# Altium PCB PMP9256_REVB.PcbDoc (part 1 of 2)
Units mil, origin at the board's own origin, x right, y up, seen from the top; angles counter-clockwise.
Board outline 5025 x 2070 mil, 4 copper layers (Top Layer, Signal Layer 1, Signal Layer 2, Bottom Layer), stack 61.2 mil thick; 115 components, 45 nets, 247 pads, 260 vias.
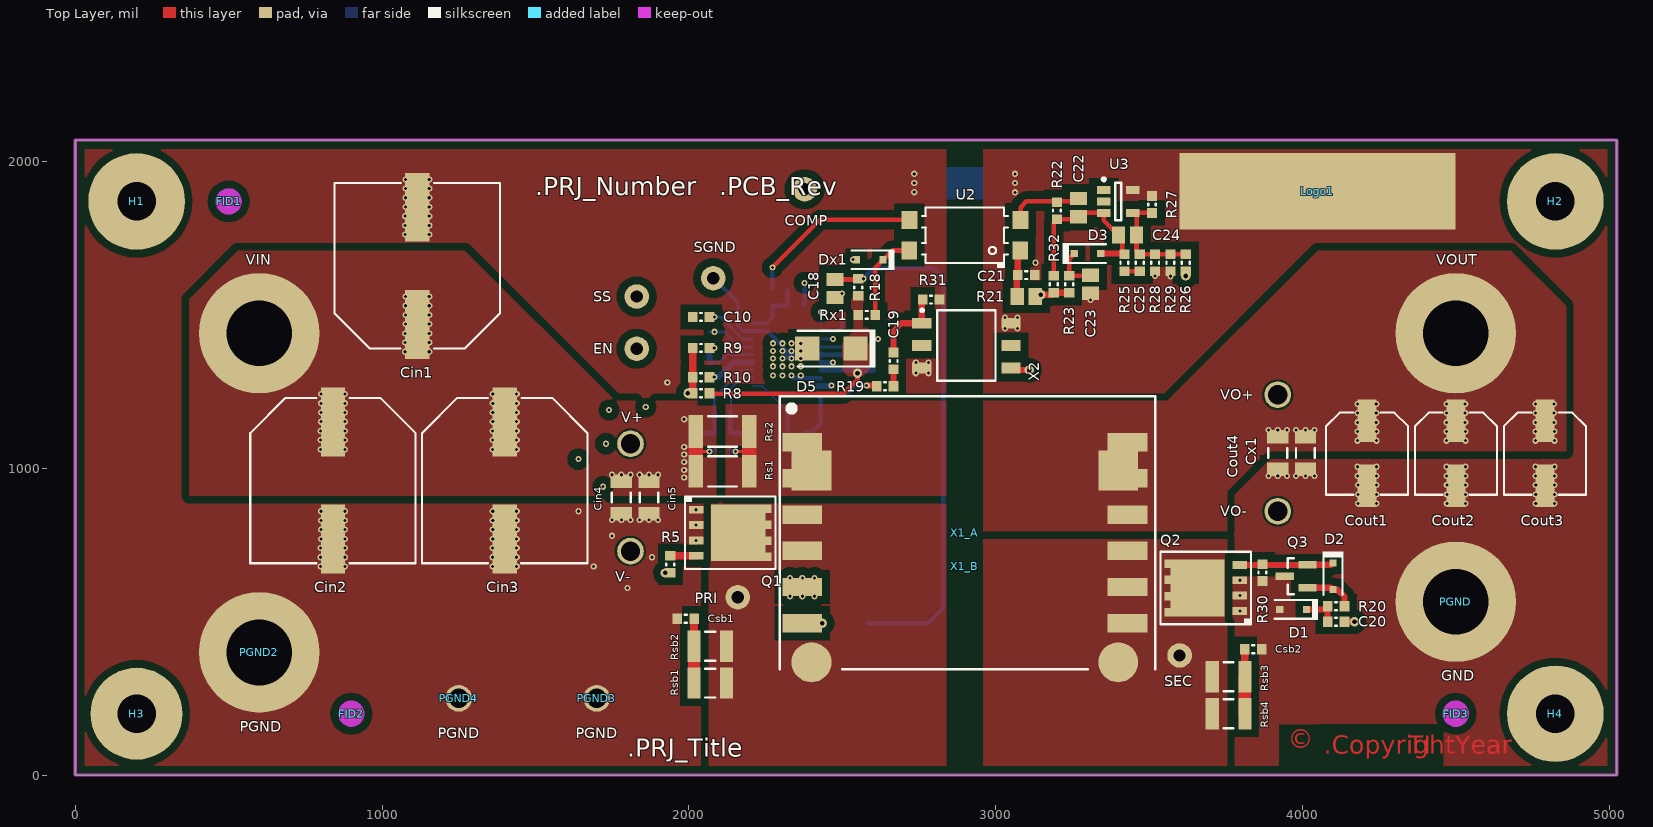
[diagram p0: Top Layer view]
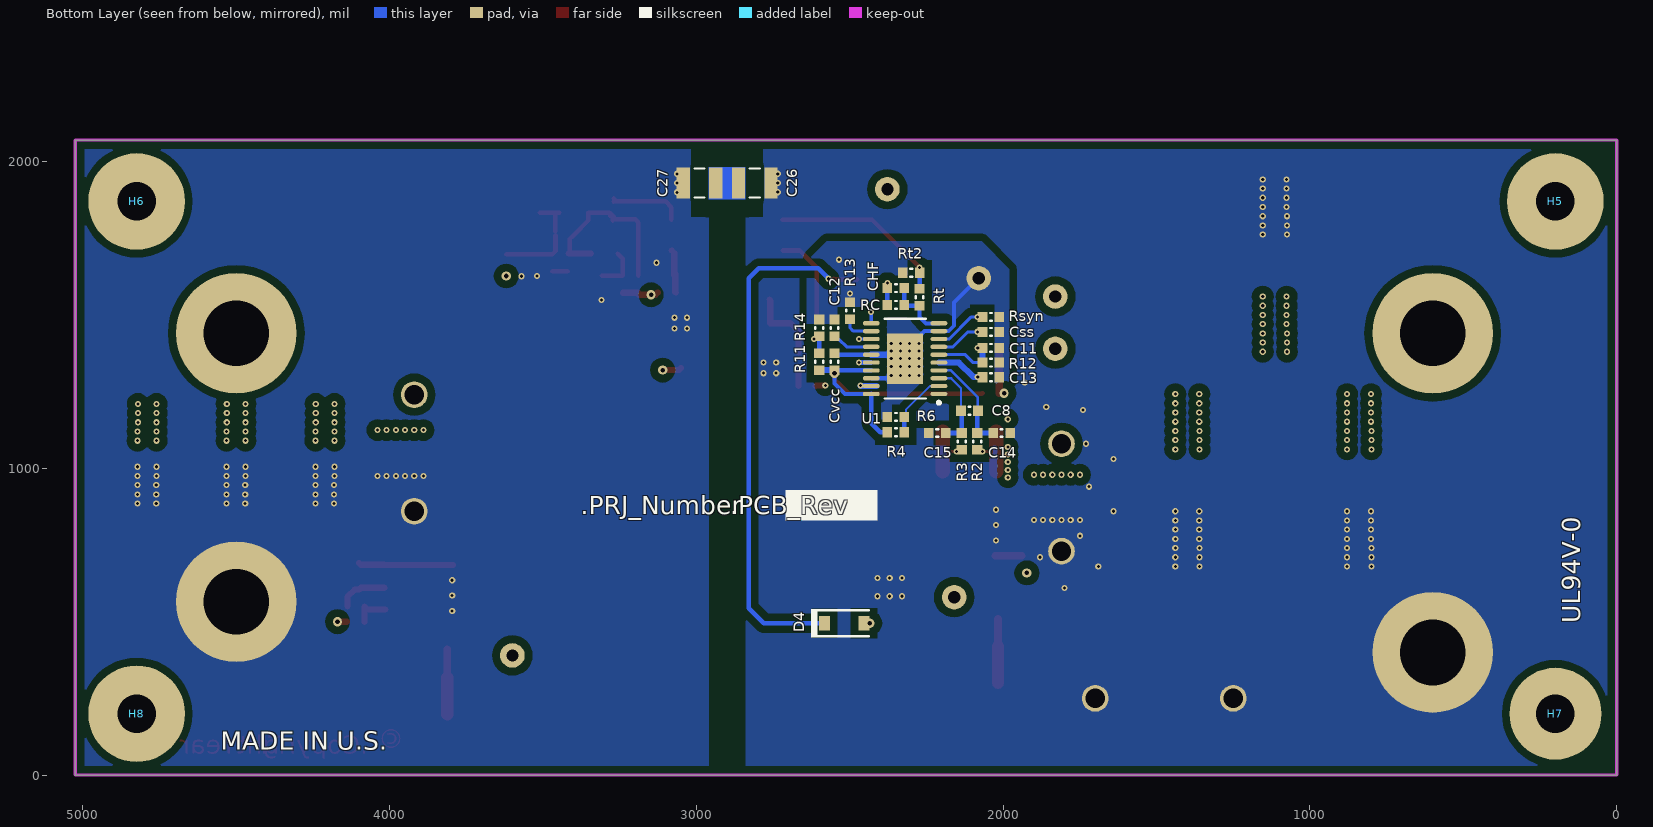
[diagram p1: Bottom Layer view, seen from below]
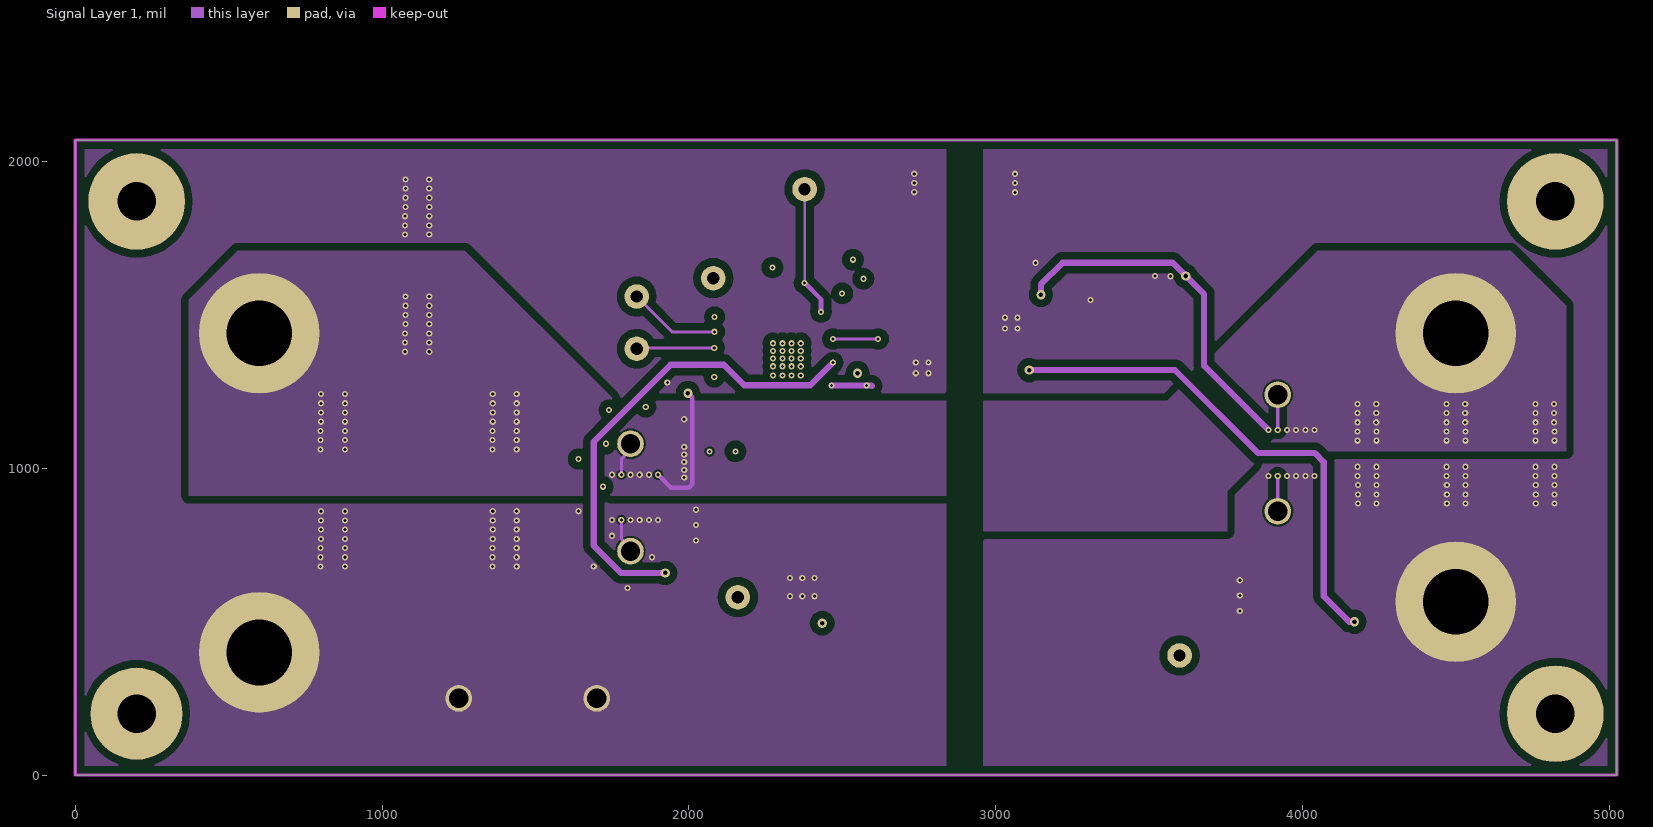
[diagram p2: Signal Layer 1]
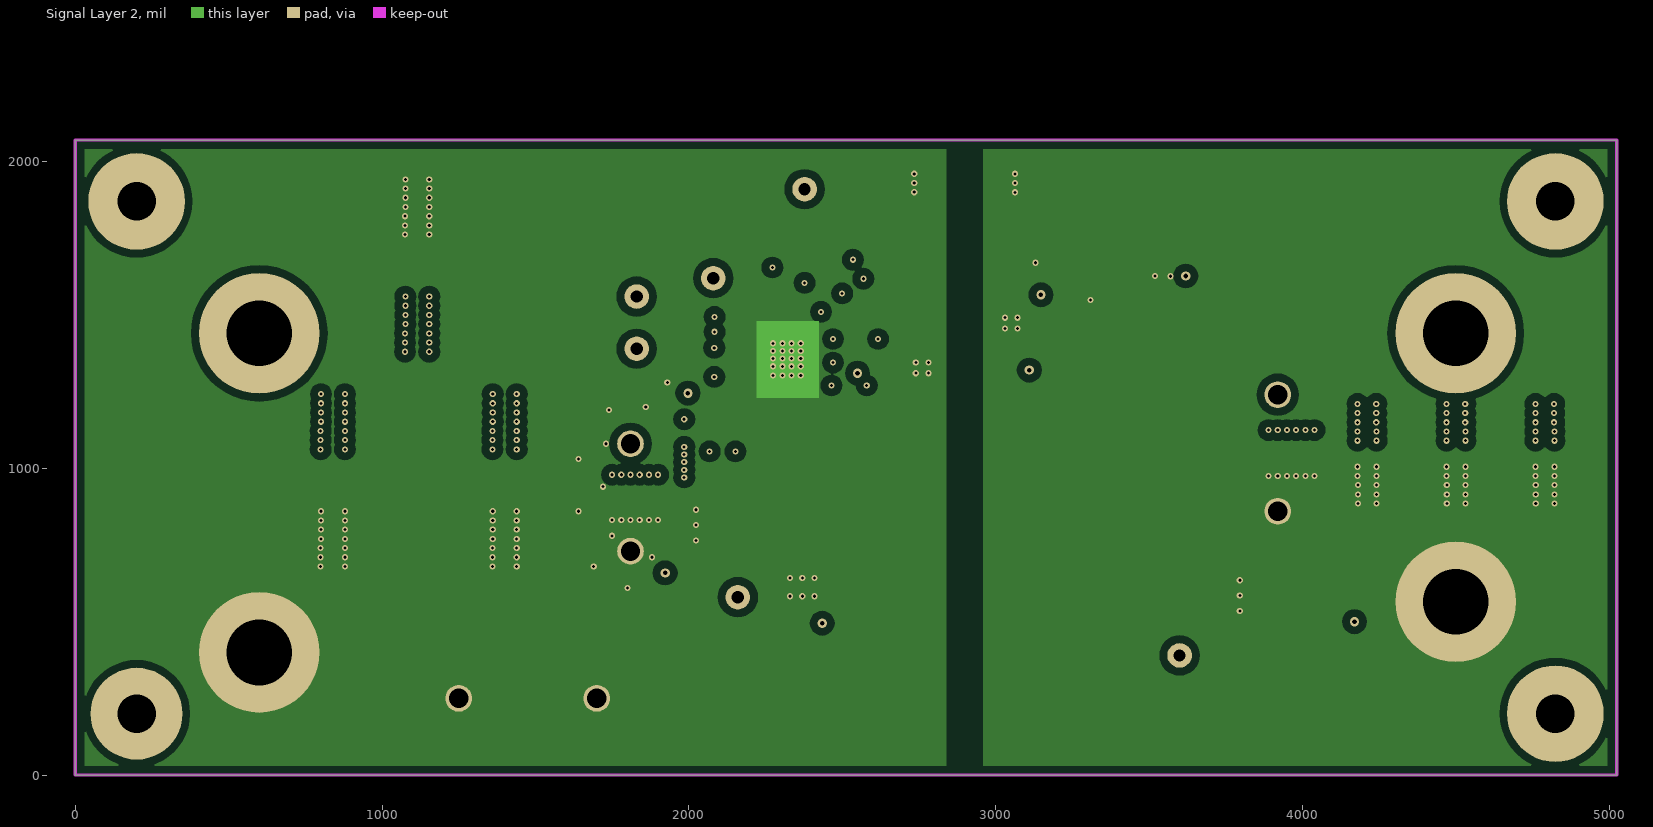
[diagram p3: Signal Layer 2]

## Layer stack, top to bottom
Top Solder: solder mask 0.4, Solder Resist, Dk 3.5
Top Layer: signal copper 1.4
Dielectric1: core 10, FR-4, Dk 4.8
Signal Layer 1: signal copper 0.7
Dielectric 3: prepreg 37, FR-4, Dk 4.2
Signal Layer 2: signal copper 0.7
Dielectric 2: core 10, FR-4, Dk 4.2
Bottom Layer: signal copper 1.4
Bottom Solder: solder mask 0.4, Solder Resist, Dk 3.5

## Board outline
0,0 5025,0 5025,2070 0,2070

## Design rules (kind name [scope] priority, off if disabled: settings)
AcuteAngle [All] p1: minimum=4.50000000000000E+0001 checktracksonly=FALSE
AssemblyTestPointUsage [All] p1: valid=2
Clearance Clearance_1 [InNet('ISO')] p1: gap=60
Clearance Clearance_Keepouts [((IsTrack Or IsArc) And Not InPoly) And IsFree and IsKeepOut vs ((IsTrack Or IsArc) And Not InPoly) And IsFree and IsKeepOut] p2: gap=0
Clearance Clearance_BoardEdge_MountingHoles [OnCopper and InComponentClass('Mounting Holes') vs IsKeepOut] p3: gap=35
Clearance Clearance_BoardEdge_Poly [OnCopper and InPoly vs IsKeepOut] p4: gap=25
Clearance Clearance_BoardEdge [OnCopper and Not InComponentClass('Logo') and not InComponentClass('FiducialMark') and not InRegion(1000,500,4000,800) and Not IsKeepout vs IsKeepOut] p5: gap=75
Clearance Clearance_Poly [InPolygon] p6: gap=25
Clearance [All] p7: gap=7.87
ComponentClearance ComponentClearance_X1 [HasFootprint('PA2398NL') vs HasFootprint('PA6605-AL')] p1: gap=0 collisioncheckmode=3 verticalgap=0 showdistances=FALSE
ComponentClearance ComponentClearance_MountingHoles_FiducialMarks [InComponentClass('Mounting Holes') vs InComponentClass('FiducialMark')] p2: gap=50 collisioncheckmode=3 verticalgap=10 showdistances=FALSE
ComponentClearance ComponentClearance_Shunt [InComponentClass('Header') vs InComponentClass('Shunt')] p3: gap=0 collisioncheckmode=3 verticalgap=0 showdistances=FALSE
ComponentClearance ComponentClearance_Logo [InComponentClass('Logo')] p4: gap=50 collisioncheckmode=3 verticalgap=10 showdistances=FALSE
ComponentClearance ComponentClearance_ScrewToNut [(HasFootprint('NY PMS 440 0025 PH')) vs (HasFootprint('Keystone_1902C'))] p5: gap=5 collisioncheckmode=3 verticalgap=10 showdistances=FALSE
ComponentClearance ComponentClearance_MountingHoles [InComponentClass('Mounting Holes')] p6: gap=150 collisioncheckmode=3 verticalgap=100000 showdistances=FALSE
ComponentClearance ComponentClearance_SmallPassives [HasFootprint('0201*') or HasFootprint('0402*') or HasFootprint('0508') or HasFootprint('0603*') or HasFootprint('0612') or HasFootprint('0805*') or HasFootprint('0815*') or HasFootprint('0830*') or HasFootprint('1206*') or HasFootprint('1210*') or HasFootprint('1808*') or HasFootprint('1812*') or HasFootprint('1825*') or HasFootprint('2010*') or HasFootprint('2220*') or HasFootprint('2225*') or HasFootprint('2512*') or HasFootprint('2728*') or HasFootprint('3518*') vs HasFootprint('0201*') or HasFootprint('0402*') or HasFootprint('0508') or HasFootprint('0603*') or HasFootprint('0612') or HasFootprint('0805*') or HasFootprint('0815*') or HasFootprint('0830*') or HasFootprint('1206*') or HasFootprint('1210*') or HasFootprint('1808*') or HasFootprint('1812*') or HasFootprint('1825*') or HasFootprint('2010*') or HasFootprint('2220*') or HasFootprint('2225*') or HasFootprint('2512*') or HasFootprint('2728*') or HasFootprint('3518*')] p7: gap=10 collisioncheckmode=3 verticalgap=10 showdistances=FALSE
ComponentClearance ComponentClearance_THtoSMT [IsThruComponent vs IsSMTComponent] p8: gap=40 collisioncheckmode=3 verticalgap=30 showdistances=FALSE
ComponentClearance ComponentClearance_THtoTH [IsThruComponent vs IsThruComponent] p9: gap=50 collisioncheckmode=3 verticalgap=30 showdistances=FALSE
ComponentClearance [All] p10: gap=20 collisioncheckmode=3 verticalgap=10 showdistances=FALSE
DiffPairsRouting [All] p1: maxlimit=100 minlimit=10 mostfreqgap=10 toplayer_minwidth=15 toplayer_maxwidth=15 toplayer_prefwidth=15 midlayer1_minwidth=15 midlayer1_maxwidth=15 midlayer1_prefwidth=15 midlayer2_minwidth=15 midlayer2_maxwidth=15 midlayer2_prefwidth=15 bottomlayer_minwidth=15 bottomlayer_maxwidth=15 bottomlayer_prefwidth=15 maxuncoupledlength=1000
FabricationTestPointUsage TestPointUsage [All] p1: valid=2 allowmultiple=FALSE
FabricationTestpoint Testpoint [All] p1: side=3 testpointundercomponent=TRUE minsize=40 maxsize=100 preferedsize=60 minholesize=0 maxholesize=40 preferedholesize=32 testpointgrid=1 allowsidetop=TRUE allowsidebottom=TRUE usegrid=TRUE gridtolerance=0.01
FanoutControl Fanout_LCC [IsLCC] p1: bgadir=Out bgaviamode=Centered fanoutstyle=Auto fanoutdirection=Alternating viagrid=1 // Fanout_LCC (Default Rule)
FanoutControl Fanout_BGA [IsBGA] p2: bgadir=Out bgaviamode=Centered fanoutstyle=Auto fanoutdirection=Alternating viagrid=1 // Fanout_BGA (Default Rule)
FanoutControl Fanout_Default [All] p4: bgadir=Out bgaviamode=Centered fanoutstyle=Auto fanoutdirection=Alternating viagrid=1 // Fanout_Default (Default Rule)
FanoutControl Fanout_Small [(CompPinCount < 5)] p5: bgadir=Out bgaviamode=Centered fanoutstyle=Auto fanoutdirection=OutThenIn viagrid=1 // Fanout_Small (Default Rule)
HoleSize [All] p1: absolutevalues=TRUE maxlimit=251 minlimit=8 maxpercent=80.000 minpercent=20.000
MinimumAnnularRing MinimumAnnularRing_ThermalPadVias [IsVia and InAnyComponent] p1: minimumring=5
MinimumAnnularRing [All] p2: minimumring=5
MinimumSolderMaskSliver MinimumSolderMaskSliver_Logo [InComponentClass('Logo') vs InComponentClass('Logo')] p1: minsoldermaskwidth=0.7
MinimumSolderMaskSliver [All] p2: minsoldermaskwidth=3.94
PlaneConnect [All] p1: planeconnectstyle=Direct reliefexpansion=10 reliefentries=4 reliefconductorwidth=10 reliefairgap=10
PolygonConnect [All] p1: connectstyle=Direct reliefconductorwidth=10 reliefentries=4 polygonreliefangle="90 Angle" airgapwidth=10
RoutingVias ThermalPadVias [IsVia and InAnyComponent] p1: holewidth=7.87 width=19.68 viastyle="Through Hole" minholewidth=7.87 minwidth=19.68 maxholewidth=12.99 maxwidth=23.62
RoutingVias [All] p2: holewidth=16 width=20 viastyle="Through Hole" minholewidth=7.87 minwidth=20 maxholewidth=40 maxwidth=65
SilkToBoardRegionClearance [Not ((IsComment or IsDesignator) And (Hide <> 'False')) and not InRegion(1000,500,4000,800)] p1:
SilkToSilkClearance SilkToSilkClearance_Pb-FreeLogo [(HasFootprint('Pb-Free_Overlay_Medium') OR HasFootprint('Pb-Free_Overlay_Small')) vs (HasFootprint('Pb-Free_Overlay_Medium') OR HasFootprint('Pb-Free_Overlay_Small'))] p1: silktosilkclearance=0
SilkToSilkClearance [All] p2: silktosilkclearance=5
SilkToSolderMaskClearance "Silk to Solder Mask Opening" [All] p1: minsilkscreentomaskgap=1 clearancetoexposedcopper=FALSE
SolderMaskExpansion [All] p1: expansion=1.97
UnpouredPolygon [All] p1: allowunpoured=FALSE
Width [All] p1: maxlimit=100 minlimit=6 preferedwidth=10 checkconnectedcopper=TRUE
14 further rules are at their usual default settings.

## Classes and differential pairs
component class "Mounting Holes": H1 H2 H3 H4
component class Logo: Logo1
component class PMP9256_REVB_Sh2: FID1 FID2 FID3 H1 H2 H3 H4 H5 H6 H7 H8 Logo1 ZZ2 ZZ3 ZZ4
component class FiducialMark: FID1 FID2 FID3
component class AssemblyNote: ZZ2 ZZ3 ZZ4
component class PMP9256_REVB_Sh1: C8 C10 C11 C12 C13 C14 C15 C18 C19 C20 C21 C22 C23 C24 C25 C26 C27 Chf Cin1 Cin2 Cin3 Cin4 Cin5 COMP Cout1 Cout2 Cout3 Cout4 Csb1 Csb2 Css Cvcc Cx1 D1 D2 D3 D4 D5 Dx1 EN PGND PGND2 PGND3 PGND4 PRI Q1 Q2 Q3 R2 R3 R4 R5 R6 R8 R9 R10 R11 R12 R13 R14 R18 R19 R20 R21 R22 R23 R25 R26 R27 R28 R29 R30 R31 R32 Rc Rs1 Rs2 Rsb1 Rsb2 Rsb3 Rsb4 Rsyn Rt Rt2 Rx1 SEC SGND SS U1 U2 U3 V+ V- VIN VO+ VO- VOUT X1_A X1_B X2

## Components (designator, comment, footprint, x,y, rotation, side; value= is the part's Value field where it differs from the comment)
C8 "GRM1885C1H561JA01D" 0603L 2110,1187.56 r180 bottom
C10 "GRM1885C1H101JA01D" 0603L 2040,1493.56 r180 top
C11 "GRM1885C1H101JA01D" 0603L 2040,1392.56 r180 bottom
C12 "GRM188R71E473KA01D" 0603L 2550,1457.56 r90 bottom
C13 "GRM188R71E474KA12D" 0603L 2040,1296.56 r180 bottom
C14 "GRM1885C1H470JA01D" 0603L 2005,1115.12 r0 bottom
C15 "GRM1885C1H470JA01D" 0603L 2215,1115.12 r0 bottom
C18 "DNP" 0805L 2476,1586 r270 top
C19 "GRM188R71E473KA01D" 0603L 2667.56,1350 r270 top
C20 "GRM188R71E473KA01D" 0603L 4110,500 r0 top
C21 "C1608X7R1C105K" 0603L 3100,1630 r0 top
C22 "DNP" 0805L 3270,1850 r90 top
C23 "GRM21BR61C106KE15L" 0805L 3310,1600 r270 top
C24 "C2012Y5V1H105Z" 0805L 3430,1760 r0 top
C25 "GRM188R71H104KA93D" 0603L 3470,1670 r270 top
C26 "Vishay, VJ1210Y222KBRAT4X" 1210L 2810,1930 r180 bottom
C27 "VJ1210Y222KXGAT5Z" 1210L 2990,1930 r180 bottom
CHF "GRM1885C1H101JA01D" 0603L 2350,1587.56 r180 bottom (schematic designator Chf)
Cin1 "EEV-FK1J221Q" SM_RADIAL_H13 1115,1660 r90 top
Cin2 "EEV-FK1J221Q" SM_RADIAL_H13 840,960 r270 top
Cin3 "EEV-FK1J221Q" SM_RADIAL_H13 1400,960 r270 top
Cin4 "C3216X7R2A105M" 1206L 1780,905 r270 top
Cin5 "C3216X7R2A105M" 1206L 1870,905 r270 top
COMP "5002" Keystone5002 2377.56,1910 r90 top
Cout1 "20SVPF120M" CAPSMT_62_F61 4210,1050 r270 top
Cout2 "20SVPF120M" CAPSMT_62_F61 4500,1050 r270 top
Cout3 "20SVPF120M" CAPSMT_62_F61 4790,1050 r270 top
Cout4 "GRM31CR61C226KE15L" 1206L 3920,1050 r270 top
Csb1 "GRM188R72A821KA01D" 0603L 1990,510 r180 top
Csb2 "GRM188R72A821KA01D" 0603L 3840,410 r0 top
Css "GRM188R71H103KA01D" 0603L 2040,1444.56 r180 bottom
Cvcc "C0603C475K8PACTU" 0603L 2550,1347.56 r270 bottom
Cx1 "GRM31CR61C226KE15L" 1206L 4010,1050 r270 top
D1 "BAT54HT1G" sod-323 3970,540 r180 top
D2 "BAS 16-03W E6327" sod-323 4100,648 r270 top
D3 "BAS 16-03W E6327" sod-323 3300,1700 r0 top
D4 "DNP" SOD-123 2518,495 r180 bottom
D5 "DNP" SMA 2465,1390 r180 top
Dx1 "MMSZ5231BS-7-F" sod-323 2590,1680 r180 top
EN "5002" KEYSTONE5002 1830,1390 r90 top
FID1 "Fiducial" Fiducial10-20 500,1870 r0 top
FID2 "Fiducial" Fiducial10-20 900,200 r0 top
FID3 "Fiducial" Fiducial10-20 4500,200 r0 top
H1 "NY PMS 440 0025 PH" "NY PMS 440 0025 PH"#1 200,1870 r0 top locked
H2 "NY PMS 440 0025 PH" "NY PMS 440 0025 PH"#1 4825,1870 r0 top locked
H3 "NY PMS 440 0025 PH" "NY PMS 440 0025 PH"#2 200,200 r0 top locked
H4 "NY PMS 440 0025 PH" "NY PMS 440 0025 PH"#1 4825,200 r0 top locked
H5 "1902C" Keystone_1902C 200,1870 r180 bottom locked
H6 "1902C" Keystone_1902C 4825,1870 r180 bottom locked
H7 "1902C" Keystone_1902C 200,200 r180 bottom locked
H8 "1902C" Keystone_1902C 4825,200 r180 bottom locked
Logo1 "Texas Instruments" TI_Stacked_SolderMask_Small 4049.42,1903 r0 top
PGND "GND" Keystone_575-4 4500,565 r270 top
PGND2 "PGND" Keystone_575-4 600,400 r270 top
PGND3 "PGND" Keystone5011 1700,250 r90 top
PGND4 "PGND" Keystone5011 1250,250 r90 top
PRI "5002" KEYSTONE5002 2160,580 r270 top
Q1 "BSC190N15NS3 G" PG-TDSON-8 2135,790 r0 top
Q2 "BSC190N15NS3 G" PG-TDSON-8 3685,610 r180 top
Q3 "MMBT3906" SOT-23 3980,648 r180 top
R2 "CRCW0603182RFKEA" 0603L 2085,1087.56 r270 bottom
R3 "CRCW0603182RFKEA" 0603L 2135,1087.56 r270 bottom
R4 "DNP" 0603L 2350,1117.56 r0 bottom
R5 "ERJ-3GEY0R00V" 0603L 1940,687 r270 top
R6 "ERJ-3GEY0R00V" 0603L 2350,1167.56 r180 bottom
R8 "DNP" 0603L 2040,1245 r0 top
R9 "CRCW060340K2FKEA" 0603L 2040,1392.56 r180 top
R10 "CRCW06033R30JNEA" 0603L 2040,1296.56 r180 top
R11 "ERJ-3GEY0R00V" 0603L 2600,1347.56 r270 bottom
R12 "CRCW06038K66FKEA" 0603L 2040,1344.56 r0 bottom
R13 "CRCW0603100KFKEA" 0603L 2499.27,1513.86 r270 bottom
R14 "DNP" 0603L 2600,1457.56 r270 bottom
R18 "DNP" 0603L 2552.44,1590 r90 top
R19 "CRCW06032R20JNEA" 0603L 2640,1267.73 r0 top
R20 "CRCW06032R20JNEA" 0603L 4110,550 r0 top
R21 "CRCW080510R0FKEA" 0805L 3100,1560 r0 top
R22 "CRCW060310K0FKEA" 0603L 3200,1840 r90 top
R23 "CRCW060347K5FKEA" 0603L 3240,1600 r270 top
R25 "CRCW060340K2FKEA" 0603L 3420,1670 r270 top
R26 "CRCW060341K2FKEA" 0603L 3620,1670 r270 top
R27 "CRCW06034K75FKEA" 0603L 3510,1860 r270 top
R28 "DNP" 0603L 3520,1670 r90 top
R29 "DNP" 0603L 3570,1670 r90 top
R30 "CRCW06031K00FKEA" 0603L 3870,660 r90 top
R31 "CRCW06034K99FKEA" 0603L 2790,1550 r180 top
R32 "DNP" 0603L 3190,1600 r90 top
RC "CRCW060320K0FKEA" 0603L 2350,1532.56 r0 bottom (schematic designator Rc)
Rs1 "WSL2010R0100FEA18" 2010L 2110,990 r0 top
Rs2 "WSL2010R0100FEA18" 2010L 2110,1120 r0 top
Rsb1 "ERJ-14NF34R0U" 1210L 2070,300 r0 top
Rsb2 "ERJ-14NF34R0U" 1210L 2070,420 r0 top
Rsb3 "ERJ-14NF34R0U" 1210L 3760,320 r180 top
Rsb4 "ERJ-14NF34R0U" 1210L 3760,200 r180 top
Rsyn "CRCW060340K2FKEA" 0603L 2040,1493.56 r0 bottom
Rt "CRCW060310K0FKEA" 0603L 2273,1557.56 r270 bottom
Rt2 "CRCW06031K00FKEA" 0603L 2300,1637.56 r180 bottom
Rx1 "CRCW06031K00FKEA" 0603L 2580,1500 r180 top
SEC "5002" KEYSTONE5002 3600,390 r270 top
SGND "SGND" KEYSTONE5001 2080,1620 r90 top
SS "5002" Keystone5002 1830,1560 r90 top
U1 "LM5122" MXA20A_L 2320,1357.56 r0 bottom
U2 "FOD817ASD" N04C 2900,1760 r180 top
U3 "TI, LMV431ACM5" MF05A_N 3400,1870 r0 top
V+ "5010" Keystone5010 1810,1080 r270 top
V- "5011" Keystone5011 1810,730 r90 top
VIN "575-4" Keystone_575-4 600,1440 r270 top
VO+ "5010" Keystone5010 3920,1240 r0 top
VO- "5011" Keystone5011 3920,860 r0 top
VOUT "575-4" Keystone_575-4 4500,1440 r270 top
X1_A "DNP" PA2398NL 2900,790 r270 top
X1_B "PA6605-AL" PA6605-AL 2900,680 r0 top
X2 "DA2319-ALB" DA2319-ALB 2905,1400 r0 top
ZZ2 "These assemblies are ESD sensitive, ESD precautions shall be observed." AssemblyNote 185,3829.11 r0 top
ZZ3 "These assemblies must be clean and free from flux and all contaminants. Use of no clean flux is not acceptable." AssemblyNote 185,3740.56 r0 top
ZZ4 "These assemblies must comply with workmanship standards IPC-A-610 Class 2, unless otherwise specified." AssemblyNote 185,3652 r0 top

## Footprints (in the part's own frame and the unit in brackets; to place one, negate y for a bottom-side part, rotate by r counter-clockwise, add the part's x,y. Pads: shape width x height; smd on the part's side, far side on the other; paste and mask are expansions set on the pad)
0603L [mm] "0603 from SM-752 data"
  rect 0.8x0.85 smd: 1(-0.7,0) 2(0.7,0)
  silkscreen extent -0.07,-0.33 0.07,0.33, body extent -0.87,-0.47 0.87,0.47, height 0.85
0805L [mm] "0805 from SM-752 data"
  rect 1.1x1.4 smd: 1(-0.75,0) 2(0.75,0)
  body extent -1.1,-0.72 1.1,0.72, height 1.1
1206L [mm] "1206 from SM-752 data"
  rect 1.1x1.75 smd: 1(-1.35,0) 2(1.35,0)
  silkscreen extent -0.4,-0.77 0.4,0.77, body extent -1.7,-0.9 1.7,0.9, height 1.35
1210L [mm] "1210 from SM-752 data"
  rect 1.1x2.6 smd: 1(-1.35,0) 2(1.35,0)
  silkscreen extent -0.4,-1.2 0.4,1.2, body extent -1.7,-1.35 1.7,1.35, height 1.35
2010L [mm]
  rect 1.2x2.7 smd: 1(-2.2,0) 2(2.2,0)
  silkscreen extent -1.2,-1.25 1.2,1.25, body extent -2.73,-1.45 2.73,1.45, height 1.66
AssemblyNote [mil] "Assembly Note"
CAPSMT_62_F61 [mm] "6.3 x 5.8mm:  Chemi-Con F61"
  rect 3.5x1.6 smd: 1(-2.675,0.025) 2(2.725,0.025)
  silkscreen extent -3.34,-3.38 3.46,3.42, body extent -3.39,-3.39 3.46,3.43, height 6.1
DA2319-ALB [mil] "Gate Transformer"
  rect 63x35 smd: 1(-145.5,73) 2(-145.5,0) 3(-145.5,-73) 4(145.5,-73) 5(145.5,0) 6(145.5,73)
  silkscreen extent -148,-115 95,119, body extent -162,-110 162,110, height 213
Fiducial10-20 [mm]
  round 1 smd mask+0.5: 1(0,0)
  Top Layer keep-out circle w1.178: c0,0 r0.5
KEYSTONE5001 [mil] "For Keystone 500x miniature loop terminals"
  round 80 hole 40: 1(0,0)
  body extent -49,-49 49,49, height 182
Keystone5002 [mil] "For Keystone 500x miniature loop terminals"
  round 80 hole 40: 1(0,0)
  body extent -49,-49 49,49, height 182
KEYSTONE5002 [mil] "For Keystone 500x miniature loop terminals"
  round 80 hole 40: 1(0,0)
  body extent -49,-49 49,49, height 182
Keystone5010 [mil] "Keystone Multipurpose loops"
  round 87 hole 63: 1(0,0)
  body extent -63,-63 63,62, height 319
Keystone5011 [mil] "Keystone Multipurpose loops"
  round 87 hole 63: 1(0,0)
  body extent -63,-63 63,62, height 319
Keystone_575-4 [mm] "Banana Jack"
  round 10 hole 5.45: 1(0,0)
  body extent -3.95,-3.95 3.92,3.93, height 2.36
Keystone_1902C [mil] "Hex Standoff, 4-40 threaded, nylon"
  body extent -145,-126 146,126, height 501
MF05A_N [mm] "SOT23, 5-Leads, Body 2.9x1.6mm, Pitch 0.95mm, Lead Span 2.8mm, IPC Medium Density"
  rect 1.1x0.65 smd: 1(-1.2,0.95) 2(-1.2,0) 3(-1.2,-0.95) 4(1.2,-0.95) 5(1.2,0.95)
  silkscreen extent -1.32,-1.55 0.25,1.95, body extent -0.9,-1.55 0.9,1.55, height 1.19
MXA20A_L [mm] "TSOP, 20-Leads, Body 6.5x4.4mm, Pitch 0.65mm, Exposed Pad, IPC High Density"
  oval 1.4x0.35 smd: 1(-2.8,2.925) 2(-2.8,2.275) 3(-2.8,1.625) 4(-2.8,0.975) 5(-2.8,0.325) 6(-2.8,-0.325) 7(-2.8,-0.975) 8(-2.8,-1.625) 9(-2.8,-2.275) 10(-2.8,-2.925) 11(2.8,-2.925) 12(2.8,-2.275) 13(2.8,-1.625) 14(2.8,-0.975) 15(2.8,-0.325) 16(2.8,0.325) 17(2.8,0.975) 18(2.8,1.625) 19(2.8,2.275) 20(2.8,2.925)
  rect 3x4.2 smd: 21(0,0)
  silkscreen extent -2.92,-3.3 1.7,3.77, body extent -2.25,-3.3 2.25,3.3, height 1.1
N04C [mm] "FAIRCHILD"
  rect 1.3x1.5 smd mask+0.065: 1(-4.587,1.27) 2(-4.612,-1.27) 3(4.588,-1.27) 4(4.613,1.27)
  silkscreen extent -3.56,-2.3 3.56,2.72, body extent -5.08,-2.3 5.08,2.3, height 3.87
"NY PMS 440 0025 PH"#1 [mm] "4-40 nylon screw and mounting hole"
  round 8 hole 3.2: ""(0,0)
  body extent -3.3,-3.3 3.3,3.3, height 2.69
"NY PMS 440 0025 PH"#2 [mm] "4-40 nylon screw and mounting hole"
  round 7.62 hole 3.2: ""(0,0)
  body extent -3.3,-3.3 3.3,3.3, height 2.69
PA2398NL [mil] "Transformer"
  rect 60x130 smd: 1(-295,-530) 2(-177,-530) 3(-59,-530) 4(59,-530) 5(177,-530) 6(295,-530) 7(295,530) 8(177,530) 9(59,530) 10(-59,530) 11(-177,530) 12(-295,530)
  silkscreen extent -445,-603 445,620, body extent -430,-575 430,575, height 450
PA6605-AL [mil] "Transformer"
  rect 130x130 smd: 1(-500,312.5) 4(500,312.5)
  round 130 smd: 2(-500,-312.5) 3(500,-312.5)
  body extent -590,-525 590,525, height 536
PG-TDSON-8 [mm] "Infineon recommended land pattern"
  rect 1.2x0.65 smd: 1(-2.825,1.905) 2(-2.825,0.635) 3(-2.825,-0.635) 4(-2.825,-1.905)
  rect 0.5x0.7 smd: 5(3.175,-2) 6(3.175,-0.675) 7(3.175,0.675) 8(3.175,2)
  rect 4.5x4.7 smd paste-2.25: 9(0.675,0)
  silkscreen extent -3.74,-3 3.74,3, body extent -3.17,-2.89 3.17,2.9, height 1.1
SM_RADIAL_H13 [mm] "12.5 x 13.5mm:  Panasonic H13"
  rect 5.7x2 smd: 1(-4.85,0) 2(4.85,0)
  silkscreen extent -6.85,-6.85 6.85,6.85, body extent -6.85,-6.85 6.85,6.85, height 14
SMA [mm] "Molded Diode, 2-Leads, Body 4.3x2.6mm, IPC Medium Density, based on OnSemi component dimensions and land pattern"
  rect 2x2 smd: 1(-2,0) 2(2,0)
  silkscreen extent -3.66,-1.57 2.79,1.57, body extent -2.6,-1.3 2.6,1.3, height 2.42
SOD-123 [mm] "On Semi recommended land pattern"
  rect 0.915x1.22 smd: 1(-1.637,0) 2(1.637,0)
  silkscreen extent -2.74,-1.17 2.03,1.17, body extent -1.93,-0.9 1.93,0.9, height 1.35
sod-323 [mm] "NXP recommended land pattern"
  rect 0.6x0.6 smd paste-0.05: 1(-1.1,0) 2(1.1,0)
  silkscreen extent -2.06,-0.86 1.53,0.86, body extent -1.3,-0.67 1.3,0.68, height 1.1
SOT-23 [mm] "SOT23, 3-Leads, Body 2.9x1.3mm, Pitch 0.95mm, Lead Span 2.5mm, IPC Medium Density"
  rect 1.5x0.6 smd: 1(-0.95,0.95) 2(-0.95,-0.95) 3(0.95,0)
  silkscreen extent 0.2,-1.5 0.7,1.5, body extent -1.16,-1.45 1.21,1.45, height 1
TI_Stacked_SolderMask_Small [mil]
  rect 900x250 smd paste-125 mask-125: 0(0,0)

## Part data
C8: "CAP, CERM, 560pF, 50V, +/-5%, C0G/NP0, 0603"
C10 C11 CHF: "CAP, CERM, 100pF, 50V, +/-5%, C0G/NP0, 0603"
C12: "CAP, CERM, 0.047uF, 25V, +/-10%, X7R, 0603"
C13: "CAP, CERM, 0.47uF, 25V, +/-10%, X7R, 0603"
C14 C15: "CAP, CERM, 47pF, 50V, +/-5%, C0G/NP0, 0603"
C18: library part GRM21BR61C106KE15L, "CAP, CERM, 10uF, 16V, +/-10%, X5R, 0805"
C19 C20: "CAP, CERM, 0.047 µF, 25 V, +/- 10%, X7R, 0603"
C21: "CAP, CERM, 1uF, 16V, +/-10%, X7R, 0603"
C22: library part C2012Y5V1H105Z, "Capacitor"
C23: "CAP, CERM, 10uF, 16V, +/-10%, X5R, 0805"
C24: "Capacitor"
C25: "CAP, CERM, 0.1uF, 50V, +/-10%, X7R, 0603"
C26: library part VJ1210Y222KXGAT5Z, "CAP, CERM, 2200pF, 1000V, +/-10%, X7R, 1210"
C27: "CAP, CERM, 2200pF, 1000V, +/-10%, X7R, 1210"
Cin1 Cin2 Cin3: "CAP, AL, 220uF, 63V, +/-20%, 0.16 ohm, SMD"
Cin4 Cin5: "CAP, CERM, 1uF, 100V, +/-20%, C Series, 1206"
COMP EN SS: "Test Point, TH, Miniature, White"
Cout1 Cout2 Cout3: "CAP, AL, 120uF, 20V, +/-20%, 0.025 ohm, SMD"
Cout4 Cx1: "CAP, CERM, 22uF, 16V, +/-10%, X5R, 1206"
Csb1 Csb2: "CAP, CERM, 820 pF, 100 V, +/- 10%, X7R, 0603"
Css: "CAP, CERM, 0.01uF, 50V, +/-10%, X7R, 0603"
Cvcc: "CAP, CERM, 4.7uF, 10V, +/-10%, X5R, 0603"
D1: "Diode, Schottky, 30V, 0.2A, SOD-323"
D2 D3: library part Diode, "DIODE SWITCH 80V 0.25A SOD323-2"
D4: library part BAV21W-7-F, "Diode, Switching, 200V, 0.2A, SOD-123"
D5: library part BZG03C15G, "Diode, Zener, 15V, 1.5W, SMA"
Dx1: "Diode, Zener, 5.1 V, 200 mW, SOD-323"
FID1 FID2 FID3: "Fiducial mark.  There is nothing to buy or mount."
H1 H2 H3 H4: "Machine Screw, Round, #4-40 x 1/4, Nylon, Philips panhead"
H5 H6 H7 H8: "Standoff, Hex, 0.5\"L #4-40 Nylon"
Logo1: library part TI_Logo, "Texas Instrument Corporate Signature"
PGND PGND2: library part 575-4, "Standard Banana Jack, Uninsulated, 5.5mm"
PGND3 PGND4: library part 5011, "Test Point, TH, Multipurpose, Black"
PRI SEC: "Test Point, Miniature, White, TH"
Q1 Q2: "MOSFET, N-CH, 150 V, 50 A, PG-TDSON-8"
Q3: library part "MMBT3906, Fairchild Semiconductor", "Transistor, PNP, 40V, 0.2A, SOT-23"
R2 R3: "RES, 182 ohm, 1%, 0.1W, 0603"
R4: library part CRCW0603158KFKEA, "RES, 158 k, 1%, 0.1 W, 0603"
R5 R6 R11: "RES, 0 ohm, 5%, 0.1W, 0603"
R8 R14: library part ERJ-3GEY0R00V, "RES, 0, 5%, 0.1 W, 0603"
R9 R25 Rsyn: "RES, 40.2k ohm, 1%, 0.1W, 0603"
R10: "RES, 3.3 ohm, 5%, 0.1W, 0603"
R12: "RES, 8.66k ohm, 1%, 0.1W, 0603"
R13: "RES, 100k ohm, 1%, 0.1W, 0603"
R18: library part CRCW06030000Z0EA, "RES, 0 ohm, 5%, 0.1W, 0603"
R19 R20: "RES, 2.2 ohm, 5%, 0.1W, 0603"
R21: "RES, 10.0 ohm, 1%, 0.125W, 0805"
R22: "RES, 10.0k ohm, 1%, 0.1W, 0603"
R23: "RES, 47.5k ohm, 1%, 0.1W, 0603"
R26: "RES, 41.2k ohm, 1%, 0.1W, 0603"
R27: "RES, 4.75 k, 1%, 0.1 W, 0603"
R28: library part CRCW06032K26FKEA, "RES, 2.26k ohm, 1%, 0.1W, 0603"
R29: library part CRCW0603442RFKEA, "RES, 442 ohm, 1%, 0.1W, 0603"
R30: "RES, 1.00k ohm, 1%, 0.1W, 0603"
R31: "RES, 4.99k ohm, 1%, 0.1W, 0603"
R32: library part CRCW060310K0FKEA, "RES, 10.0k ohm, 1%, 0.1W, 0603"
RC: "RES, 20.0k ohm, 1%, 0.1W, 0603"
Rs1 Rs2: "RES, 0.01 ohm, 1%, 1W, 2010"
Rsb1 Rsb2 Rsb3 Rsb4: library part MCR25JZHJ000, "RES 34 OHM 1/2W 1% 1210 SMD"
Rt: "RES, 10.0 k, 1%, 0.1 W, 0603"
Rt2 Rx1: "RES, 1.00 k, 1%, 0.1 W, 0603"
SGND: library part 5001, "Test Point, TH, Miniature, Black"
U2: "IC, Optocoupler, 5000V, 80-160% CTR"
U3: library part LMV431ACM5, "Low-Voltage (1.24V) Adjustable Precision Shunt Regulator, 5-pin SOT-23"
V+ VO+: "Test Point, Multipurpose, Red, TH"
V- VO-: "Test Point, TH, Multipurpose, Black"
VIN VOUT: "Standard Banana Jack, Uninsulated, 5.5mm"
X1_A: library part PA2398
X1_B: library part PA6605
ZZ2 ZZ3 ZZ4: library part AssemblyNote

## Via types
v1: diameter 20, hole 10, Top Layer to Bottom Layer, tented both sides, 252 vias
v2: diameter 30, hole 15, Top Layer to Bottom Layer, tented both sides, 8 vias

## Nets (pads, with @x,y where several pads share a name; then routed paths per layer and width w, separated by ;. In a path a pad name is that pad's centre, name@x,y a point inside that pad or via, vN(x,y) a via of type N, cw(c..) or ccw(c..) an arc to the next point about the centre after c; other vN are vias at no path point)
COMP: CHF.1 COMP.1 RC.2 U1.11 | length 514.7
  Signal Layer 1 w8: v1(2377.56,1604.56) COMP.1@2377.56,1910
  Signal Layer 1 w15: v1(2377.56,1604.56) 2431,1551.12 v1(2431,1510)
  Bottom Layer w12.5: U1.11@2430.24,1472.72 2430.24,1509.24 v1(2431,1510)
  Bottom Layer w15: RC.2@2377.56,1532.56 CHF.1@2377.56,1587.56
CSN: C8.1 C15.1 R3.1 U1.3 | length 285
  Bottom Layer w8: C8.1@2140,1190 C8.1@2137.56,1187.56 2137.56,1261.14 2170,1293.58 U1.3@2209.76,1293.58
  Bottom Layer w15: C8.1@2135,1185 R3.1@2135,1115.12 C15.1@2187.44,1115.12
CSP: C8.2 C14.2 R2.1 U1.4 | length 329.6
  Bottom Layer w8: C8.2@2082.44,1187.56 2082.44,1231 2170.61,1319.17 U1.4@2209.76,1319.17
  Bottom Layer w15: C14.2@2032.56,1115.12 R2.1@2085,1115.12 C8.2@2085,1185
EXT_SYNC: C10.2
FB: CHF.2 RC.1 Rt.2 U1.10 | length 200.6
  Bottom Layer w13: U1.10@2209.76,1472.72 2252.16,1472.72 2272.47,1493.03 Rt.2@2272.47,1530
  Bottom Layer w15: Rt.2@2272.7,1529.77 RC.1@2318.31,1529.77 ; RC.1@2322.31,1533.77 CHF.2@2322.31,1580.64
HO: R19.1 U1.19 | length 218.3
  Top Layer w20: v1(2580,1270) 2610.17,1270 R19.1@2612.44,1267.73
  Signal Layer 1 w20: v1(2465,1270) v1(2580,1270) 2594.73,1270 2597,1267.73
  Bottom Layer w20: U1.19@2413,1267.99 v1@2465,1267.99
ISO: C26.1 C27.2
"ISO GND": C21.2 C23.2 C27.1 Cout1.2 Cout2.2 Cout3.2 Cout4.2 Csb2.2 Cx1.2 D1.2 Logo1.0 PGND.1 Q2.1 Q2.2 Q2.3 Q3.3 R27.1 R28.1 R29.1 R30.1 U3.5 VO-.1 X2.6 | length 114.5
  Signal Layer 1 w10: VO-.1@3920,860 v1(3920,974.5)
  other v1: 3796.22,535 3796.22,585 3796.22,635 4181,885 4242,885 4471,885 4532,885 4761,885 4822,885 4181,915 4242,915 4471,915 4532,915 4761,915 4822,915 4181,945 4242,945 4471,945 4532,945 4761,945 4822,945 3890,974.5 3950,974.5 4180,975 4242,975 4470,975 4532,975 4760,975 4822,975 3980,975.5 4010,975.5 4040,975.5 4180,1005 4242,1005 4470,1005 4532,1005 4760,1005 4822,1005 3031,1456 3072,1456 3031,1491 3072,1491 3310,1548.5 3570,1626 3520,1627 3130,1670 3064,1899.74 3064,1930 3064,1960
LO: R5.2 U1.16 | length 1590.8
  Signal Layer 1 w20: v2(1923,659) 1779,659 1690,748 1690,1086.79 1940.77,1337.56 2114,1337.56 2181,1270.56 2395.8,1270.56 v1(2470,1344.76)
  Bottom Layer w15: U1.16@2430.24,1344.76 v1(2470,1344.76)
MODE: R11.1 R14.2 U1.13 | length 241.6
  Signal Layer 1 w10: v1@2470,1421.56 v1(2617,1421.56)
  Bottom Layer w10: U1.13@2430.24,1421.54 v1(2470,1421.54)
  Bottom Layer w15: R11.1@2600,1375.12 R14.2@2600,1430
NetC18_1: C18.1 D4.1 R18.2 | length 1707.6
  Top Layer w15: C18.1@2476,1615.53 2550.41,1615.53 R18.2@2552.44,1617.56
  Bottom Layer w15: v1(2569,1618) 2603,1652 2796.64,1652 2829.42,1619.22 2829.42,544.42 2780,495 D4.1@2582.47,495
NetC19_1: C19.1 R31.2 X2.1 | length 250.7
  Top Layer w20: C19.1@2667.56,1377.56 2667.56,1447.56 2693,1473 X2.1@2759.5,1473 2759.5,1547.06 R31.2@2762.44,1550
NetC19_2: C19.2 R19.2 | length 54.7
  Top Layer w20: R19.2@2667.56,1267.73 C19.2@2667.56,1322.44
NetC20_1: C20.1 D1.1 R20.1 | length 123.3
  Top Layer w20: D1.1@4013.31,540 4072.44,540 R20.1@4082.44,550 C20.1@4082.44,500
NetC20_2: C20.2 X2.4 | length 1748
  Top Layer w20: X2.4@3050.5,1327 3057.5,1320 v2(3110,1320) ; C20.2@4140,500 v2(4170,500)
  Signal Layer 1 w20: v2(3110,1320) 3585,1320 3855,1050 4040,1050 4070,1020 4070,583 4153,500 v2(4170,500)
NetC21_1: C21.1 R21.1 U2.1 | length 144.2
  Top Layer w20: R21.1@3067.28,1573.31 3069.25,1575.27 C21.1@3069.25,1633.31 ; C21.1@3072.44,1630 3072.44,1701.83 U2.1@3080.61,1710
NetC22_1: C22.1 C24.1 D3.2 R22.1 R25.1 R32.2 U3.3 | length 602.2
  Top Layer w10: R25.1@3417.56,1700 R25.1@3420,1697.56
  Top Layer w15: R32.2@3190,1627.56 3190,1802.44 R22.1@3200,1812.44 3270,1812.44 C22.1@3280.16,1822.6 ; C22.1@3270,1810.47 C22.1@3272.76,1807.72 ; C22.1@3270,1820.47 3282.13,1832.6 U3.3@3352.76,1832.6 3352.76,1807.72 C24.1@3400.47,1760 3413,1747.47 3413,1704.56 R25.1@3417.56,1700
  Top Layer w20: D3.2@3343.31,1700 R25.1@3417.56,1700
NetC22_2: C22.2 R22.2 U2.2 | length 251.3
  Top Layer w15: U2.2@3081.59,1810 3081.59,1851.59 3100,1870 C22.2@3260.47,1870 ; C22.2@3270,1869.53 3269.53,1870 C22.2@3260.47,1870 ; C22.2@3270,1879.53 C22.2@3260.47,1870
NetC23_1: C23.1 D3.1 R23.1 | length 150.2
  Top Layer w10: C23.1@3308.03,1627.56 C23.1@3310,1629.53
  Top Layer w15: D3.1@3256.69,1700 3240,1683.31 R23.1@3240,1627.56 C23.1@3308.03,1627.56
NetC24_2: C24.2 C25.1 R26.1 R27.2 R28.2 R29.2 U3.4 | length 339.9
  Top Layer w15: U3.4@3447.24,1832.6 3447.4,1832.44 R27.2@3510,1832.44 ; C24.2@3459.53,1760 3459.53,1708.03 C25.1@3470,1697.56 R26.1@3620,1697.56 ; C24.2@3460,1772.13 U3.4@3460,1832.44
NetC25_2: C25.2 R25.2 | length 50
  Top Layer w15: R25.2@3420,1642.44 C25.2@3470,1642.44
NetCsb1_1: Csb1.1 Rsb1.1 Rsb2.1 | length 210
  Top Layer w25: Rsb2.1@2016.85,420 Csb1.1@2016.85,510
  Top Layer w40: Rsb1.1@2016.85,300 Rsb2.1@2016.85,420
NetCsb2_1: Csb2.1 Rsb3.1 Rsb4.1 | length 212.3
  Top Layer w25: Rsb3.1@3812.44,317.71 Csb2.1@3812.44,410
  Top Layer w40: Rsb4.1@3812.44,197.71 Rsb3.1@3812.44,317.71
NetD2_1: D2.1 Q2.4 Q3.2 R30.2 | length 307.5
  Top Layer w20: Q2.4@3794.5,685 Q3.2@4017,685 ; Q3.2@4017.4,685.4 4094.09,685.4 D2.1@4100,691.31
NetD2_2: D2.2 Q3.1 R20.2 | length 163.4
  Top Layer w20: Q3.1@4017.4,610.6 4094.09,610.6 D2.2@4100,604.69 4113.77,604.69 4137.56,580.9 R20.2@4137.56,550
NetD4_2: D4.2 X1_A.6
  other v2: 2435,495
NetDx1_1: Dx1.1 Rx1.1 U2.4 | length 288.2
  Top Layer w15: Rx1.1@2607.56,1500 2607.56,1654.25 Dx1.1@2633.31,1680 2663.31,1710 U2.4@2718.41,1710
NetQ1_4: Q1.4 R5.1 | length 85.5
  Top Layer w25: R5.1@1940,715 Q1.4@2025.5,715
NetRt2_2: Rt2.2 Rt.1 U2.3 | length 563.2
  Top Layer w15: v1(2272.44,1654.56) 2427.88,1810 U2.3@2719.39,1810
  Bottom Layer w15: Rt.1@2272.44,1585.68 Rt2.2@2272.44,1637.56
OPT: R4.1 R6.2 U1.2 | length 217.8
  Bottom Layer w6: U1.2@2209.76,1267.99 2239.57,1267.99 2317,1190.56 2317,1167.56 R6.2@2322.44,1167.56
  Bottom Layer w15: R4.1@2322.44,1117.56 R6.2@2322.44,1167.56
PGND: C14.1 C15.2 C26.2 Cin1.2 Cin2.2 Cin3.2 Cin4.2 Cin5.2 Csb1.2 PGND2.1 PGND3.1 PGND4.1 Q1.1 Q1.2 Q1.3 R31.1 V-.1 X1_A.5 X2.3 | length 113.4
  Signal Layer 1 w10: v1(1780,831) 1780,770.79 1810,740.79 V-.1@1810,730
  other v1: 2330,583 2370,583 2410,583 1800,610 2330,643 2370,643 2410,643 800,680 879,680 1360,680 1439,680 1690,680 800,710 879,710 1360,710 1439,710 1880,710 800,740 879,740 1360,740 1439,740 2023.78,765 801,770 879,770 1361,770 1439,770 1750,780 801,800 879,800 1361,800 1439,800 2023.78,815 801,830 879,830 1361,830 1439,830 1750,831 1810,831 1840,831 1870,831 1900,831 801,860 879,860 1361,860 1439,860 1640,860 2023.78,865 1720,940 1640,1030 1730,1080 1740,1190 1859.61,1200 1930,1280 2740,1310 2781,1310 2740,1345 2781,1345 1075,1761.89 1154,1761.89 1075,1791.89 1154,1791.89 1075,1821.89 1154,1821.89 1076,1851.89 1154,1851.89 1076,1881.89 1154,1881.89 2735,1900.1 1076,1911.89 1154,1911.89 2735,1930 1076,1941.89 1154,1941.89 2735,1960.08
Q1-D: PRI.1 Q1.5 Q1.6 Q1.7 Q1.8 Q1.9 Rsb1.2 Rsb2.2 X1_A.3 X1_A.4 X1_B.2
Q2-D: Q2.5 Q2.6 Q2.7 Q2.8 Q2.9 Rsb3.2 Rsb4.2 SEC.1 X1_A.7 X1_A.8 X1_A.9 X1_B.3
RES: C12.1 U1.14 | length 133.9
  Bottom Layer w10: U1.14@2430.24,1395.94 2510.39,1395.94 2534,1419.56 2539.56,1419.56 C12.1@2550,1430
